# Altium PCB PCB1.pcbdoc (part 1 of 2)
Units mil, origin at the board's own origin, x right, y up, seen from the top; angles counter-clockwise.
Board outline 2441 x 2440.7 mil, 2 copper layers (Top Layer, Bottom Layer), stack 62.2 mil thick; 65 components, 50 nets, 327 pads, 148 vias.
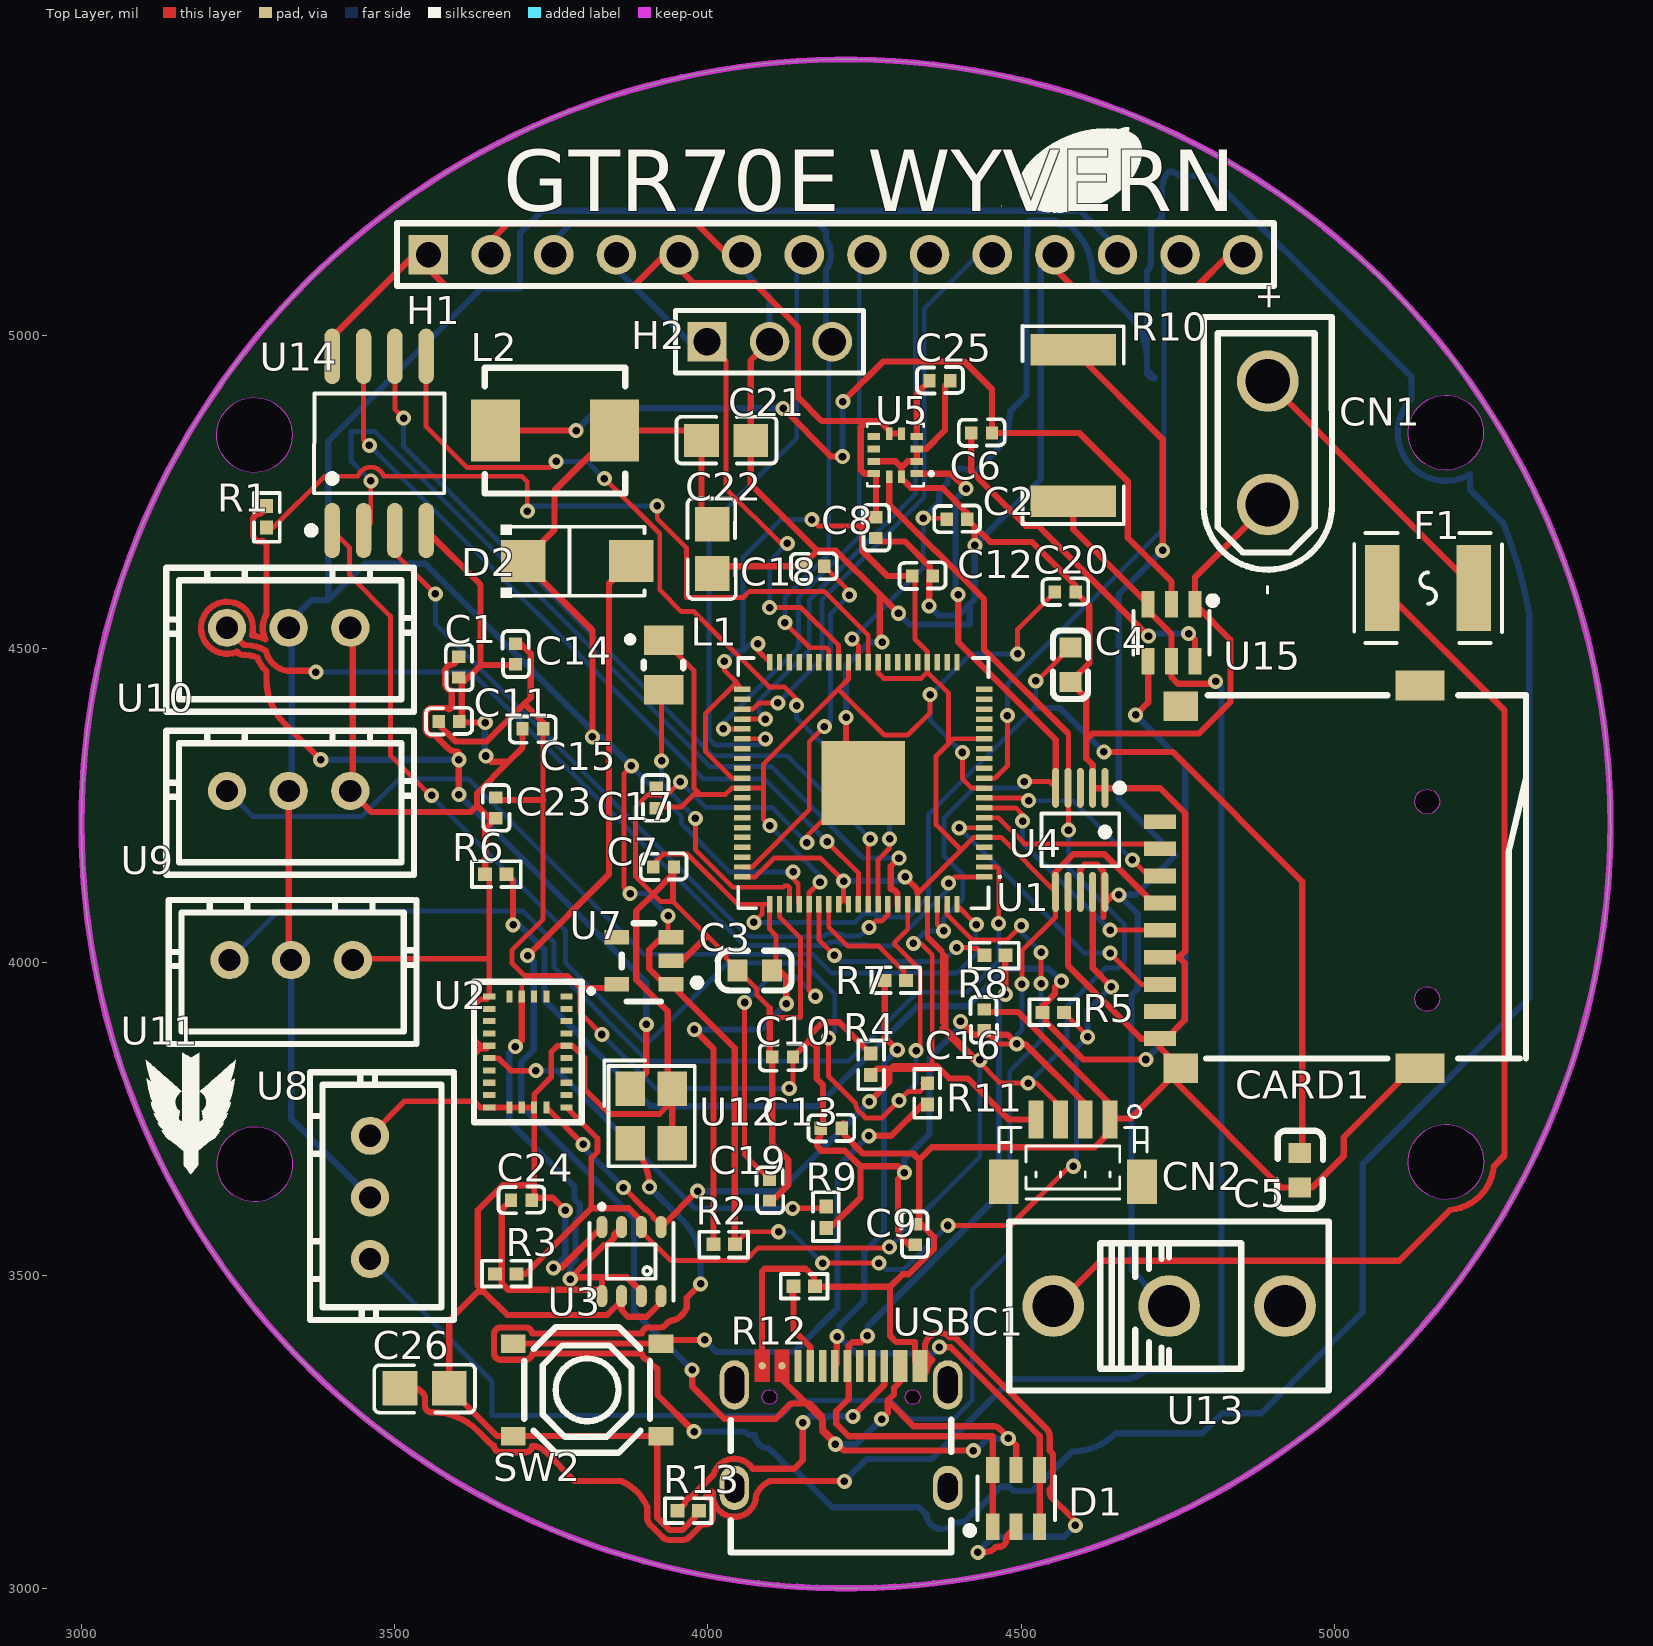
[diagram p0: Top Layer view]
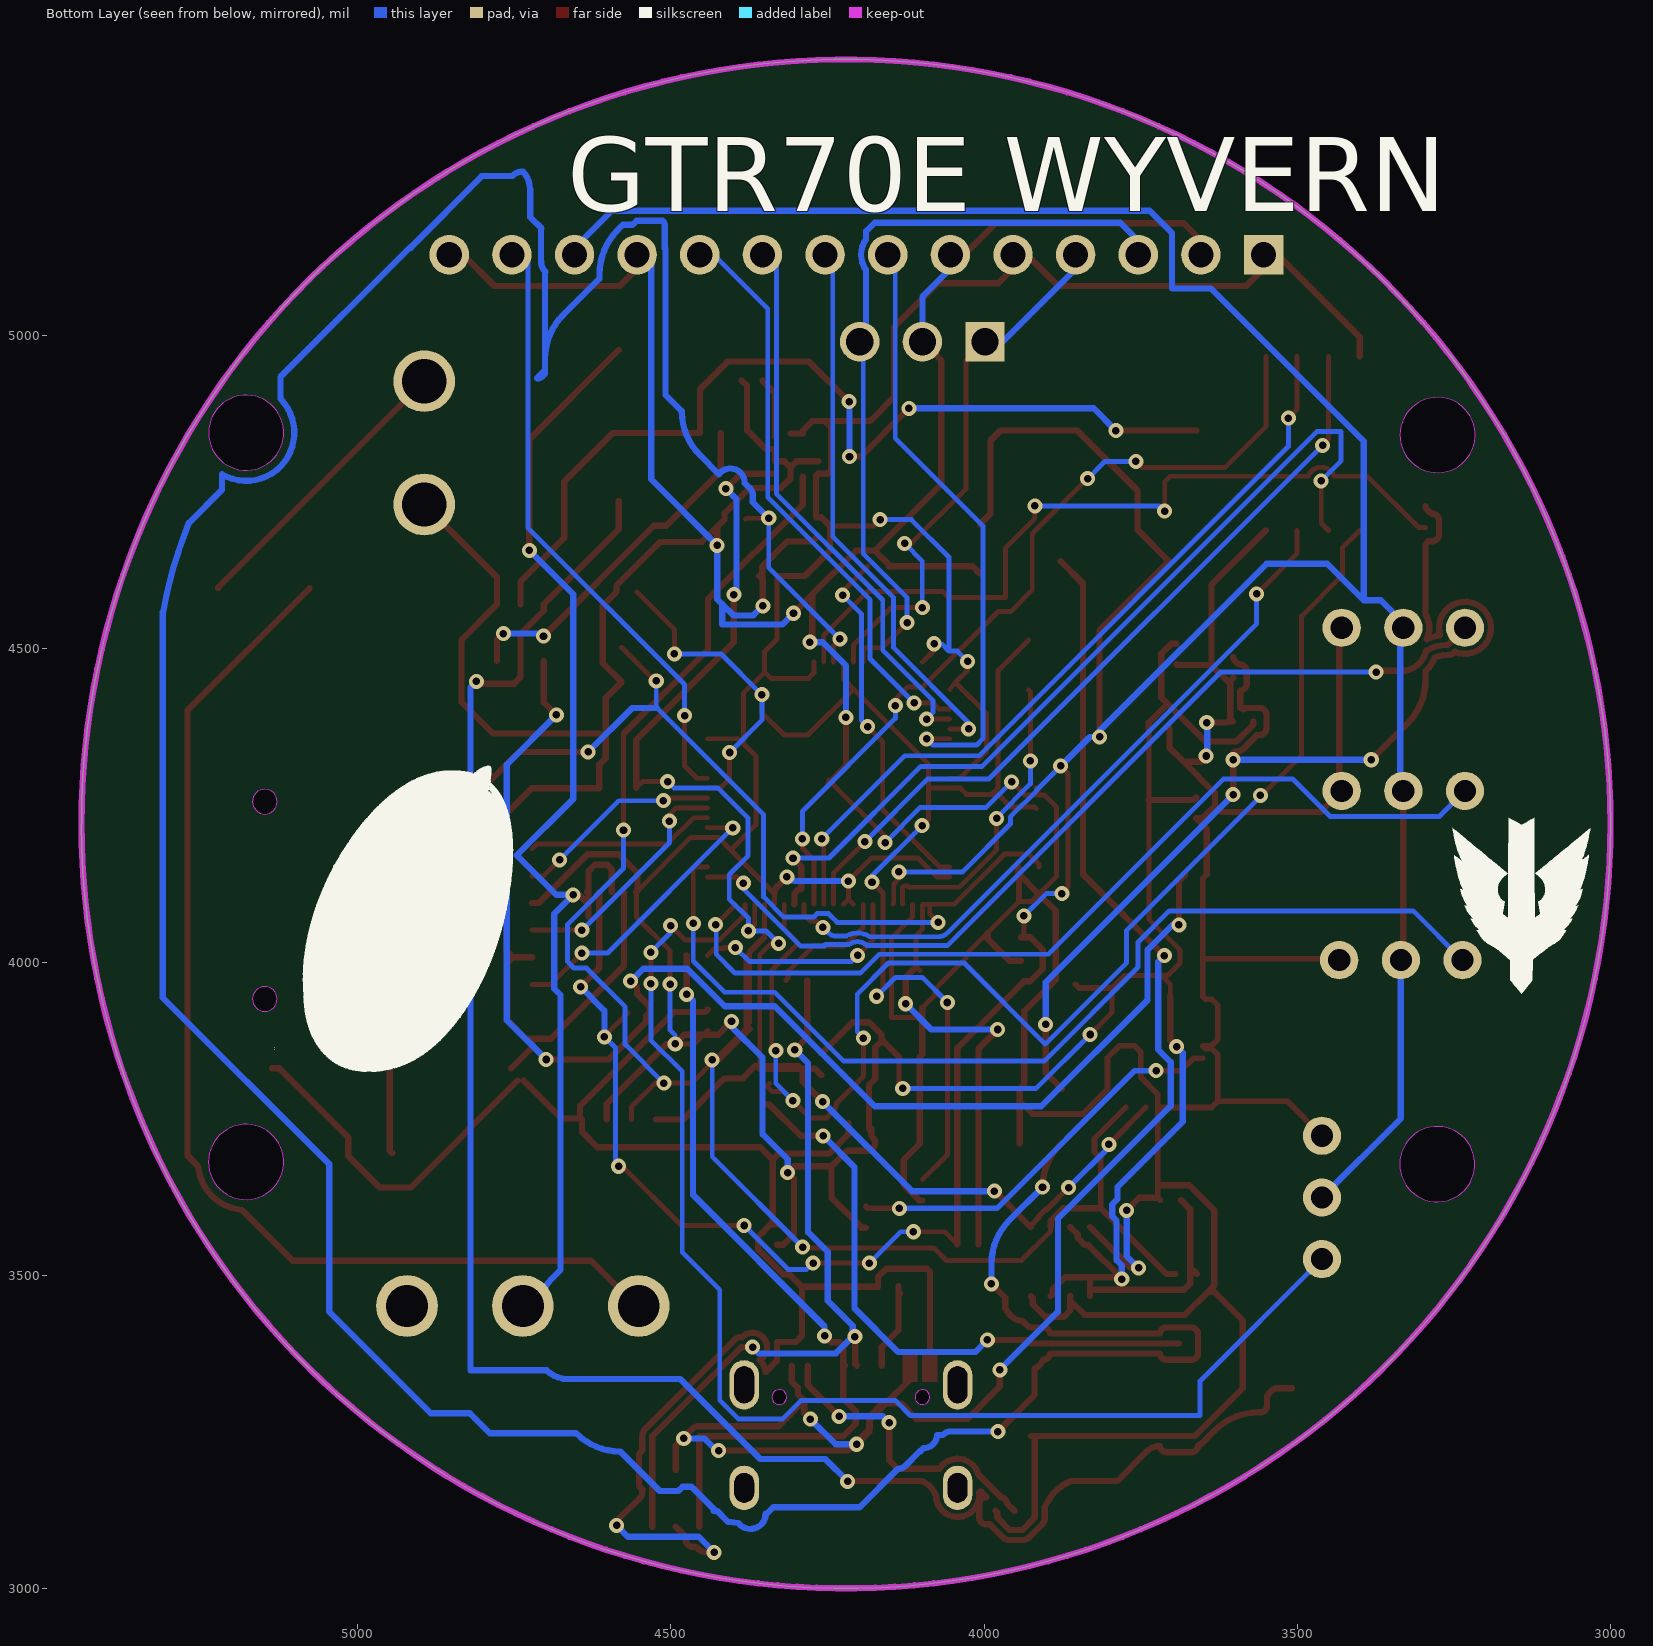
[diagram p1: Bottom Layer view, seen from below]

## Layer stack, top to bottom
Top Solder Mask Layer: solder mask 0.4, Dk 3.3
Top Layer: signal copper 1.4
Dielectric1: surface 59.4, FR4, Dk 4.5
Bottom Layer: signal copper 1.4
Bottom Solder Mask Layer: solder mask 0.4, Dk 3.3

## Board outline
5440.9,4220.5 ccw(c4220.5,4220.5) 3000,4220.5 ccw(c4220.5,4220.5)
cut-out: 3336.2,4841.4 3335.8,4834.5 3334.7,4827.8 3332.7,4821.2 3330.1,4814.9 3326.7,4808.9 3322.7,4803.4 3318,4798.3 3312.8,4793.8 3307.2,4789.9 3301.1,4786.7 3294.7,4784.3 3288.1,4782.5 3281.3,4781.5 3274.5,4781.3 3267.6,4781.9 3260.9,4783.3 3254.4,4785.4 3248.2,4788.3 3242.3,4791.8 3236.9,4796 3231.9,4800.8 3227.6,4806.1 3223.9,4811.8 3220.9,4818 3218.6,4824.4 3217,4831.1 3216.2,4837.9 3216.2,4844.8 3217,4851.6 3218.6,4858.3 3220.9,4864.7 3223.9,4870.9 3227.6,4876.7 3231.9,4882 3236.9,4886.7 3242.3,4890.9 3248.2,4894.5 3254.4,4897.3 3260.9,4899.4 3267.6,4900.8 3274.5,4901.4 3281.3,4901.2 3288.1,4900.2 3294.7,4898.5 3301.1,4896 3307.2,4892.8 3312.8,4888.9 3318,4884.4 3322.7,4879.4 3326.7,4873.8 3330.1,4867.9 3332.7,4861.5 3334.7,4855 3335.8,4848.2
cut-out: 5238,4845 5237.6,4838.1 5236.5,4831.4 5234.5,4824.8 5231.9,4818.5 5228.5,4812.5 5224.5,4807 5219.8,4801.9 5214.7,4797.4 5209,4793.5 5202.9,4790.3 5196.5,4787.9 5189.9,4786.1 5183.1,4785.1 5176.3,4784.9 5169.4,4785.5 5162.7,4786.9 5156.2,4789 5150,4791.9 5144.1,4795.4 5138.7,4799.6 5133.8,4804.4 5129.4,4809.7 5125.7,4815.4 5122.7,4821.6 5120.4,4828.1 5118.8,4834.7 5118,4841.5 5118,4848.4 5118.8,4855.2 5120.4,4861.9 5122.7,4868.3 5125.7,4874.5 5129.4,4880.3 5133.8,4885.6 5138.7,4890.3 5144.1,4894.5 5150,4898.1 5156.2,4900.9 5162.7,4903 5169.4,4904.4 5176.3,4905 5183.1,4904.8 5189.9,4903.8 5196.5,4902.1 5202.9,4899.6 5209,4896.4 5214.7,4892.5 5219.8,4888 5224.5,4883 5228.5,4877.4 5231.9,4871.5 5234.5,4865.1 5236.5,4858.6 5237.6,4851.8
cut-out: 3336.6,3677.2 3336.2,3670.4 3335,3663.6 3333.1,3657.1 3330.4,3650.7 3327,3644.8 3323,3639.2 3318.4,3634.2 3313.2,3629.7 3307.5,3625.8 3301.5,3622.6 3295.1,3620.1 3288.5,3618.4 3281.7,3617.4 3274.8,3617.2 3268,3617.8 3261.3,3619.2 3254.8,3621.3 3248.5,3624.1 3242.6,3627.7 3237.2,3631.9 3232.3,3636.6 3228,3641.9 3224.3,3647.7 3221.2,3653.9 3218.9,3660.3 3217.4,3667 3216.6,3673.8 3216.6,3680.7 3217.4,3687.5 3218.9,3694.2 3221.2,3700.6 3224.3,3706.8 3228,3712.5 3232.3,3717.8 3237.2,3722.6 3242.6,3726.8 3248.5,3730.3 3254.8,3733.2 3261.3,3735.3 3268,3736.7 3274.8,3737.3 3281.7,3737.1 3288.5,3736.1 3295.1,3734.3 3301.5,3731.9 3307.5,3728.7 3313.2,3724.8 3318.4,3720.3 3323,3715.2 3327,3709.7 3330.4,3703.7 3333.1,3697.4 3335,3690.8 3336.2,3684.1
cut-out: 5238.4,3680.8 5238,3674 5236.8,3667.2 5234.9,3660.7 5232.2,3654.3 5228.9,3648.4 5224.8,3642.8 5220.2,3637.8 5215,3633.3 5209.4,3629.4 5203.3,3626.2 5196.9,3623.7 5190.3,3622 5183.5,3621 5176.6,3620.8 5169.8,3621.4 5163.1,3622.8 5156.6,3624.9 5150.3,3627.7 5144.5,3631.3 5139,3635.5 5134.1,3640.2 5129.8,3645.5 5126.1,3651.3 5123,3657.5 5120.7,3663.9 5119.2,3670.6 5118.4,3677.4 5118.4,3684.3 5119.2,3691.1 5120.7,3697.8 5123,3704.2 5126.1,3710.4 5129.8,3716.1 5134.1,3721.4 5139,3726.2 5144.5,3730.4 5150.3,3733.9 5156.6,3736.8 5163.1,3738.9 5169.8,3740.3 5176.6,3740.9 5183.5,3740.7 5190.3,3739.7 5196.9,3737.9 5203.3,3735.5 5209.4,3732.3 5215,3728.4 5220.2,3723.9 5224.8,3718.8 5228.9,3713.3 5232.2,3707.3 5234.9,3701 5236.8,3694.4 5238,3687.7

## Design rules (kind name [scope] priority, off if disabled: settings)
BoardOutlineClearance safeClearance [All] p0: genericclearance=10 ignorepadtopadclearanceinfootprint=FALSE except(0: Arc-SplitContinuation Track-SplitContinuation SMDPad-SplitContinuation THPad-SplitContinuation Via-SplitContinuation Fill-SplitContinuation Poly-SplitContinuation Region-SplitContinuation Text-SplitContinuation)
BoardOutlineClearance otherClearance [All] p0: genericclearance=10 ignorepadtopadclearanceinfootprint=FALSE except(0: Arc-SplitContinuation Track-SplitContinuation SMDPad-SplitContinuation THPad-SplitContinuation Via-SplitContinuation Fill-SplitContinuation Poly-SplitContinuation Region-SplitContinuation Text-SplitContinuation)
Clearance safeClearance [All] p1: gap=7 ignorepadtopadclearanceinfootprint=FALSE
Clearance otherClearance [All] p1: gap=7 ignorepadtopadclearanceinfootprint=FALSE
DiffPairsRouting differentialPair [All] p1: maxuncoupledlength=10 minlimit=6 maxlimit=Infinity mostfreqgap=6 toplayer_minwidth=5 toplayer_prefwidth=10 toplayer_maxwidth=100 bottomlayer_minwidth=5 bottomlayer_prefwidth=10 bottomlayer_maxwidth=100
PasteMaskExpansion pasteMaskExpansion [All] p1: expansion=0
PlaneConnect innerPlane [All] p1: planeconnectstyle=Relief reliefexpansion=20 reliefentries=4 reliefconductorwidth=10 reliefairgap=10
PolygonConnect copperRegion [All] p1: connectstyle=Relief reliefentries=4 reliefconductorwidth=10 polygonreliefangle="90 Angle" airgapwidth=10
RoutingVias viaSize [All] p1: viastyle="Through Hole" holewidth=12.0078 minholewidth=11.811 maxholewidth=236.2204 width=12.0078 minwidth=11.811 maxwidth=236.2204
SolderMaskExpansion solderMaskExpansion [IsVia] p1: useseparateexpansions=TRUE expansion=-1000 expansionbottom=-1000
SolderMaskExpansion solderMaskExpansion [All] p2: useseparateexpansions=TRUE expansion=0.9843 expansionbottom=2.0079
Width trackWidth [All] p1: maxlimit=100 minlimit=5 preferedwidth=10

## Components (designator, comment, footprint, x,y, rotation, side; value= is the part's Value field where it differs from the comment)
C1 "15pF" C0402#1 3602.4,4470.6 r270 top
C2 "15pF" C0402#2 4397.7,4706.8 r0 top
C3 "4.7uF" C0603#1 4074.9,3986.3 r180 top
C4 "4.7uF" C0603#2 4578.8,4474.5 r270 top
C5 "4.7uF" C0603#2 4945,3667.4 r270 top
C6 "100nF" C0402#3 4437.1,4844.6 r0 top
C7 "100nF" C0402#2 3929.2,4151.7 r0 top
C8 "100nF" C0402#3 4268.2,4693.5 r270 top
C9 "100nF" C0402#3 4330.8,3565.1 r90 top
C10 "100nF" C0402#2 4119.5,3848.5 r180 top
C11 "100nF" C0402#1 3586.7,4384 r0 top
C12 "100nF" C0402#1 4342.6,4616.3 r0 top
C13 "100nF" C0402#2 4196.9,3734.4 r0 top
C14 "100nF" C0402#1 3692.8,4491.8 r270 top
C15 "100nF" C0402#2 3720.6,4372.2 r180 top
C16 "100nF" C0402#1 4441,3907.6 r90 top
C17 "100nF" C0402#2 3917.4,4261.9 r90 top
C18 "100nF" C0402#2 4169.4,4632 r180 top
C19 "100nF" C0402#3 4098.5,3635.9 r270 top
C20 "100nF" C0402#3 4570.5,4590.6 r0 top
C21 "22uF" C0805#1 4029.2,4832.6 r0 top
C22 "22uF" C0805#2 4006.6,4659.6 r270 top
C23 "100nF" C0402#2 3661.5,4246.2 r270 top
C24 "100nF" C0402#3 3702.2,3619.7 r0 top
C25 "100nF" C0402#2 4370.4,4928.2 r0 top
C26 "10uF" C0805#3 3547.7,3319.7 r0 top
CARD1 "TF-01A" TF-SMD_TF-01A 4929.2,4135.9 r90 top
CN1 "XT30UPB-M" CONN-TH_XT30UPB-M 4893.8,4828.9 r90 top
CN2 "BM04B-SRSS-TB(LF)(SN)" CONN-SMD_BM04B-SRSS-TB 4582.8,3698.9 r180 top
D1 "USBLC6-2SC6" SOT-23-6_L2.9-W1.6-P0.95-LS2.8-BL#1 4492.2,3143.8 r0 top
D2 "SS14" SMA_L4.4-W2.6-LS5.0-RD 3791.4,4639.9 r0 top
F1 "SMD1812P260TF/16" F1812 5149.7,4597 r0 top
H1 "2011-1X14G00SB" HDR-TH_14P-P2.54-V-M_4 4203.9,5129.2 r0 top
H2 "2.54-1*3P针" HDR-TH_3P-P2.54-V-M-1 4098.5,4990.3 r0 top
L1 "3.3uH" IND-SMD_L2.0-W1.6_AOTA-B201610S3R3-101-T 3929.2,4474.5 r90 top
L2 "2.2uH" IND-SMD_L5.7-W5.1 3756,4848.5 r0 top
R1 "1kΩ" R0402#1 3295.4,4710.7 r90 top
R2 "33Ω" R0402#2 4026.1,3549.4 r0 top
R3 "10kΩ" R0402#2 3677.2,3502.1 r180 top
R4 "10kΩ" R0402#1 4259.9,3836.7 r90 top
R5 "56kΩ" R0402#1 4551.3,3919.4 r180 top
R6 "10.2kΩ" R0402#3 3661.5,4139.9 r180 top
R7 "27Ω" R0402#3 4299.3,3970.6 r180 top
R8 "27Ω" R0402#1 4458.3,4010.6 r0 top
R9 "10kΩ" R0402#2 4189.1,3592.6 r270 top
R10 "10mΩ" R2512 4583.1,4856.5 r270 top
R11 "1kΩ" R0402#1 4350.5,3789.5 r270 top
R12 "5.1kΩ" R0402#1 4153.6,3482.4 r0 top
R13 "5.1kΩ" R0402#2 3968.6,3124.1 r0 top
SW2 "TS-1187A-B-A-B" SW-SMD_4P-L5.1-W5.1-P3.70-LS6.5-TL_H1.5 3807.2,3317 r0 top
U1 "RP2350B" QFN-80_L10.0-W10.0-P0.40-TL-EP3.4 4248.1,4285.6 r180 top
U2 "BNO055" LGA-28_L5.2-W3.8-P0.50-BL 3712.7,3856.4 r180 top
U3 "BME680" LGA-8_L3.0-W3.0-P0.80-TR 3878,3521.8 r90 top
U4 "INA226AIDGSR" MSOP-10_L3.0-W3.0-P0.50-LS5.0-BL 4594.6,4195 r180 top
U5 "LIS3MDLTR" LGA-12_L2.0-W2.0-P0.50-BL 4299.3,4809.2 r90 top
U7 "AP2112K-3.3TRG1" SOT-23-5_L2.9-W1.6-P0.95-LS2.8-BR 3897.7,4002.1 r0 top
U8 "B3B-XH-A(LF)(SN)" CONN-TH_3P-P2.50_A2501WV2-3P#1 3460.7,3624.1 r90 top
U9 "B3B-XH-A(LF)(SN)" CONN-TH_3P-P2.50_A2501WV2-3P#2 3330.8,4273.2 r0 top
U10 "B3B-XH-A(LF)(SN)" CONN-TH_3P-P2.50_A2501WV2-3P#2 3330.8,4533.6 r0 top
U11 "B3B-XH-A(LF)(SN)" CONN-TH_3P-P2.50_A2501WV2-3P#1 3334.7,4003 r0 top
U12 "12MHz" CRYSTAL-SMD_4P-L3.2-W2.5-BL 3909.5,3754.1 r270 top
U13 "SS-12D10G5" SW-TH_SS-12D10L9 4736.3,3450.9 r0 top
U14 "W25Q32JVSSIQ" SOIC-8_L5.3-W5.3-P1.27-LS8.0-BL 3475.3,4827.9 r0 top
U15 "TPS564201DDCR" SOT-23-6_L2.9-W1.6-P0.95-LS2.8-BL#2 4740.2,4525.7 r180 top
USBC1 "TYPE-C-31-M-12" USB-C_SMD-TYPE-C-31-M-12_1 4212.7,3258 r0 top

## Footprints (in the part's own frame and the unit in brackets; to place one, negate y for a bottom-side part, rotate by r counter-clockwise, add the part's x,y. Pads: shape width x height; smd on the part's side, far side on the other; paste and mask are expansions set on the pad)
C0402#1 [mil]
  rect 19.7x21.3 smd paste+0 mask+0: 1(-16.5,0) 2(16.5,0)
  silkscreen extent -36,-21 37,22
C0402#2 [mil]
  rect 19.7x21.3 smd paste+0 mask+0: 1(-16.5,0) 2(16.6,0)
  silkscreen extent -36,-21 37,22
C0402#3 [mil]
  rect 19.7x21.3 smd paste+0 mask+0: 1(-16.6,0) 2(16.5,0)
  silkscreen extent -36,-21 37,22
C0603#1 [mil]
  rect 31.5x35.4 smd: 1(-27.5,0) 2(27.6,0)
  silkscreen extent -59,-32 59,32
C0603#2 [mil]
  rect 31.5x35.4 smd paste+0 mask+0: 1(-27.6,0) 2(27.5,0)
  silkscreen extent -55,-28 55,28
C0805#1 [mil]
  rect 55.5x53.1 smd paste+0 mask+0: 1(-39.4,0) 2(39.4,0)
  silkscreen extent -79,-37 80,38
C0805#2 [mil]
  rect 55.5x55.1 smd paste-3937 mask+0: 1(-39.4,0) 2(39.4,0)
  silkscreen extent -80,-39 80,38
C0805#3 [mil]
  rect 55.5x55.1 smd paste-3937 mask+0: 1(-39.3,0) 2(39.4,0)
  silkscreen extent -80,-39 80,38
CONN-SMD_BM04B-SRSS-TB [mil]
  rect 47.2x70.9 smd: 0(-110.2,49.7) 0(110.3,49.7)
  rect 23.6x61 smd: 1(-59,-49.7) 2(-19.6,-49.7) 3(19.7,-49.7) 4(59.1,-49.7)
  silkscreen extent -118,-72 118,77
CONN-TH_3P-P2.50_A2501WV2-3P#1 [mil]
  round 61 hole 35.4: 1(-98.4,0) 2(0,0) 3(98.5,0)
  silkscreen extent -196,-134 200,96
CONN-TH_3P-P2.50_A2501WV2-3P#2 [mil]
  round 61 hole 35.4: 1(-98.4,0) 2(0,0) 3(98.4,0)
  silkscreen extent -196,-134 200,96
CONN-TH_XT30UPB-M [mil]
  round 98.4 hole 70.9: 1(-98.5,0) 2(98.4,0)
  silkscreen extent -203,-102 201,102
CRYSTAL-SMD_4P-L3.2-W2.5-BL [mil]
  rect 55.1x47.2 smd paste+0 mask+0: 1(-43.3,-33.4) 2(43.4,-33.4) 3(43.4,33.5) 4(-43.3,33.5)
  silkscreen extent -89,-75 80,70
F1812 [mil]
  rect 55.4x137.8 smd paste-3937 mask+2: 1(-72.9,0) 2(73,0)
  silkscreen extent -118,-88 118,88
HDR-TH_3P-P2.54-V-M-1 [mil]
  rect 62x63 hole 43.3: 1(-100,0)
  round 63 hole 43.3: 2(0,0) 3(100,0)
  silkscreen extent -150,-50 150,50
HDR-TH_14P-P2.54-V-M_4 [mil]
  rect 63x63 hole 40.2: 1(-650,0)
  round 63 hole 40.2: 2(-550,0) 3(-450,0) 4(-350,0) 5(-250,0) 6(-150,0) 7(-50,0) 8(50,0) 9(150,0) 10(250,0) 11(350,0) 12(450,0) 13(550,0) 14(650,0)
  silkscreen extent -700,-50 700,50
IND-SMD_L2.0-W1.6_AOTA-B201610S3R3-101-T [mil]
  rect 47.2x63 smd paste+0 mask+0: 1(-40,0) 2(39.4,0)
  silkscreen extent -6,-32 46,58
IND-SMD_L5.7-W5.1 [mil]
  rect 78.7x98.4 smd paste+0 mask+2: 1(-95,0) 2(95,0)
  silkscreen extent -112,-100 112,100
LGA-8_L3.0-W3.0-P0.80-TR [mil]
  oval 35.4x17.6 smd paste+0 mask+0: 1(55.1,47.2) 2(55.1,15.7) 3(55.1,-15.8) 4(55.1,-47.3) 5(-55.1,-47.3) 6(-55.1,-15.8) 7(-55.1,15.7) 8(-55.1,47.2)
  silkscreen extent -62,-67 92,67
LGA-12_L2.0-W2.0-P0.50-BL [mil]
  rect 11x19.7 smd: 1(-29.6,-34.4) 2(-9.9,-34.4) 3(9.8,-34.4) 4(29.5,-34.4) 7(29.5,34.5) 8(9.8,34.5) 9(-9.9,34.5) 10(-29.6,34.5)
  rect 19.7x11 smd: 5(34.4,-9.8) 6(34.4,9.8) 11(-34.5,9.8) 12(-34.5,-9.8)
  silkscreen extent -50,-60 50,45
LGA-28_L5.2-W3.8-P0.50-BL [mil]
  rect 19.7x9.8 smd: 1(-61.5,-88.6) 6(61.6,-88.6) 7(61.6,-68.9) 8(61.6,-49.2) 9(61.6,-29.5) 10(61.6,-9.9) 11(61.6,9.8) 12(61.6,29.5) 13(61.6,49.2) 14(61.6,68.9) 15(61.6,88.6) 20(-61.5,88.6) 21(-61.5,68.9) 22(-61.5,49.2) 23(-61.5,29.5) 24(-61.5,9.8) 25(-61.5,-9.9) 26(-61.5,-29.5) 27(-61.5,-49.2) 28(-61.5,-68.9)
  rect 9.8x19.7 smd: 2(-29.5,-88.6) 3(-9.8,-88.6) 4(9.9,-88.6) 5(29.5,-88.6) 16(29.5,88.6) 17(9.9,88.6) 18(-9.8,88.6) 19(-29.5,88.6)
  silkscreen extent -105,-112 86,112
MSOP-10_L3.0-W3.0-P0.50-LS5.0-BL [mil]
  oval 11x63.8 smd paste+0 mask+0: 1(-39.3,-83.1) 2(-19.6,-83.1) 3(0,-83.1) 4(19.7,-83.1) 5(39.4,-83.1) 6(39.4,83.1) 7(19.7,83.1) 8(0,83.1) 9(-19.6,83.1) 10(-39.3,83.1)
  silkscreen extent -69,-89 62,42
QFN-80_L10.0-W10.0-P0.40-TL-EP3.4 [mil]
  rect 26.2x8.7 smd: 1(-193.2,149.7) 2(-193.2,133.9) 3(-193.2,118.2) 4(-193.2,102.4) 5(-193.2,86.7) 6(-193.2,70.9) 7(-193.2,55.2) 8(-193.2,39.4) 9(-193.2,23.7) 10(-193.2,7.9) 11(-193.2,-7.8) 12(-193.2,-23.6) 13(-193.2,-39.3) 14(-193.2,-55.1) 15(-193.2,-70.8) 16(-193.2,-86.6) 17(-193.2,-102.3) 18(-193.2,-118.1) 19(-193.2,-133.8) 20(-193.2,-149.6) 41(193.2,-149.6) 42(193.2,-133.8) 43(193.2,-118.1) 44(193.2,-102.3) 45(193.2,-86.6) 46(193.2,-70.8) 47(193.2,-55.1) 48(193.2,-39.3) 49(193.2,-23.6) 50(193.2,-7.8) 51(193.2,7.9) 52(193.2,23.7) 53(193.2,39.4) 54(193.2,55.2) 55(193.2,70.9) 56(193.2,86.7) 57(193.2,102.4) 58(193.2,118.2) 59(193.2,133.9) 60(193.2,149.7)
  rect 8.7x26.2 smd: 21(-149.6,-193.2) 22(-133.9,-193.2) 23(-118.1,-193.2) 24(-102.4,-193.2) 25(-86.6,-193.2) 26(-70.9,-193.2) 27(-55.1,-193.2) 28(-39.4,-193.2) 29(-23.6,-193.2) 30(-7.9,-193.2) 31(7.9,-193.2) 32(23.6,-193.2) 33(39.4,-193.2) 34(55.1,-193.2) 35(70.9,-193.2) 36(86.6,-193.2) 37(102.3,-193.2) 38(118.1,-193.2) 39(133.8,-193.2) 40(149.6,-193.2) 61(149.6,193.3) 62(133.8,193.3) 63(118.1,193.3) 64(102.3,193.3) 65(86.6,193.3) 66(70.9,193.3) 67(55.1,193.3) 68(39.4,193.3) 69(23.6,193.3) 70(7.9,193.3) 71(-7.9,193.3) 72(-23.6,193.3) 73(-39.4,193.3) 74(-55.1,193.3) 75(-70.9,193.3) 76(-86.6,193.3) 77(-102.4,193.3) 78(-118.1,193.3) 79(-133.9,193.3) 80(-149.6,193.3)
  rect 133.9x133.9 smd: 81(0,0)
  silkscreen extent -220,-200 200,200
R0402#1 [mil]
  rect 22.3x21.3 smd paste-3937 mask+0: 1(-17,0) 2(17.1,0)
  silkscreen extent -40,-21 38,20
R0402#2 [mil]
  rect 22.3x21.3 smd paste-3937 mask+0: 1(-17.1,0) 2(17,0)
  silkscreen extent -40,-21 38,20
R0402#3 [mil]
  rect 22.3x21.3 smd paste-3937 mask+0: 1(-17,0) 2(17,0)
  silkscreen extent -40,-21 38,20
R2512 [mil]
  rect 50.5x136.1 smd paste-3937 mask+2: 1(-120.7,0) 2(120.7,0)
  silkscreen extent -159,-81 157,81
SMA_L4.4-W2.6-LS5.0-RD [mil]
  rect 70.9x66.9 smd: 1(-86.3,0) 2(86.3,0)
  silkscreen extent -122,-58 107,58
SOIC-8_L5.3-W5.3-P1.27-LS8.0-BL [mil]
  oval 24.8x88.6 smd: 1(-75,-139) 2(-25,-139) 3(25,-139) 4(75,-139) 5(75,139) 6(25,139) 7(-25,139) 8(-75,139)
  silkscreen extent -114,-145 104,80
SOT-23-5_L2.9-W1.6-P0.95-LS2.8-BR [mil]
  rect 39.4x23.6 smd paste+0 mask+2: 1(43.3,-37.4) 2(43.3,0) 3(43.3,37.4) 4(-43.3,37.4) 5(-43.3,-37.4)
  silkscreen extent -35,-65 91,60
SOT-23-6_L2.9-W1.6-P0.95-LS2.8-BL#1 [mil]
  rect 20.9x42.2 smd: 1(-37.4,-45.2) 2(0,-45.2) 3(37.4,-45.2) 4(37.4,45.3) 5(0,45.3) 6(-37.4,45.3)
  silkscreen extent -80,-57 62,35
SOT-23-6_L2.9-W1.6-P0.95-LS2.8-BL#2 [mil]
  rect 20.9x42.2 smd: 1(-37.4,-45.2) 2(0,-45.2) 3(37.4,-45.2) 4(37.4,45.2) 5(0,45.2) 6(-37.4,45.2)
  silkscreen extent -72,-57 61,35
SW-SMD_4P-L5.1-W5.1-P3.70-LS6.5-TL_H1.5 [mil]
  rect 39.4x29.5 smd: 1(-118.1,73.9) 2(118.1,73.9) 3(-118.1,-73.8) 4(118.1,-73.8)
  silkscreen extent -100,-100 100,100
SW-TH_SS-12D10L9 [mil]
  round 98.4 hole 66.9: 1(-185,0) 2(0,0) 3(185,0)
  silkscreen extent -255,-135 255,135
TF-SMD_TF-01A [mil]
  rect 23.6x51.2 smd: 1(88.2,207.7) 2(44.9,207.7) 3(1.6,207.7) 4(-41.7,207.7) 5(-85,207.7) 6(-128.3,207.7) 7(-171.6,207.7) 8(-214.9,207.7) 9(-258.2,207.7)
  rect 47.2x55.1 smd: 10(-305.5,174.2) 13(272.5,174.2)
  rect 47.2x78.7 smd paste+0 mask+0: 11(-305.5,-207.7) 12(305.6,-207.7)
  Board Outline Layer lines w0.1: -194.8,-199.5 -198.7,-199.8 -202.4,-201 -205.8,-202.8 -208.8,-205.2 -211.2,-208.2 -213,-211.6 -214.1,-215.3 -214.5,-219.1 -214.1,-223 -213,-226.7 -211.2,-230.1 -208.8,-233.1 -205.8,-235.5 -202.4,-237.3 -198.7,-238.5 -194.8,-238.8 -191,-238.5 -187.3,-237.3 -183.9,-235.5 -180.9,-233.1 -178.5,-230.1 -176.6,-226.7 -175.5,-223 -175.2,-219.1 -175.5,-215.3 -176.6,-211.6 -178.5,-208.2 -180.9,-205.2 -183.9,-202.8 -187.3,-201 -191,-199.8 -194.8,-199.5 ; 120.1,-199.5 116.3,-199.8 112.6,-201 109.2,-202.8 106.2,-205.2 103.8,-208.2 101.9,-211.6 100.8,-215.3 100.4,-219.1 100.8,-223 101.9,-226.7 103.8,-230.1 106.2,-233.1 109.2,-235.5 112.6,-237.3 116.3,-238.5 120.1,-238.8 124,-238.5 127.7,-237.3 131.1,-235.5 134,-233.1 136.5,-230.1 138.3,-226.7 139.4,-223 139.8,-219.1 139.4,-215.3 138.3,-211.6 136.5,-208.2 134,-205.2 131.1,-202.8 127.7,-201 124,-199.8 120.1,-199.5
  Board Outline Layer region: -175.2,-219.1 -175.5,-223 -176.6,-226.7 -178.5,-230.1 -180.9,-233.1 -183.9,-235.5 -187.3,-237.3 -191,-238.5 -194.8,-238.8 -198.7,-238.5 -202.4,-237.3 -205.8,-235.5 -208.8,-233.1 -211.2,-230.1 -213,-226.7 -214.1,-223 -214.5,-219.1 -214.1,-215.3 -213,-211.6 -211.2,-208.2 -208.8,-205.2 -205.8,-202.8 -202.4,-201 -198.7,-199.8 -194.8,-199.5 -191,-199.8 -187.3,-201 -183.9,-202.8 -180.9,-205.2 -178.5,-208.2 -176.6,-211.6 -175.5,-215.3
  Board Outline Layer region: -175.2,-219.1 -175.5,-223 -176.6,-226.7 -178.5,-230.1 -180.9,-233.1 -183.9,-235.5 -187.3,-237.3 -191,-238.5 -194.8,-238.8 -198.7,-238.5 -202.4,-237.3 -205.8,-235.5 -208.8,-233.1 -211.2,-230.1 -213,-226.7 -214.1,-223 -214.5,-219.1 -214.1,-215.3 -213,-211.6 -211.2,-208.2 -208.8,-205.2 -205.8,-202.8 -202.4,-201 -198.7,-199.8 -194.8,-199.5 -191,-199.8 -187.3,-201 -183.9,-202.8 -180.9,-205.2 -178.5,-208.2 -176.6,-211.6 -175.5,-215.3
  Board Outline Layer region: 139.8,-219.1 139.4,-223 138.3,-226.7 136.5,-230.1 134,-233.1 131.1,-235.5 127.7,-237.3 124,-238.5 120.1,-238.8 116.3,-238.5 112.6,-237.3 109.2,-235.5 106.2,-233.1 103.8,-230.1 101.9,-226.7 100.8,-223 100.4,-219.1 100.8,-215.3 101.9,-211.6 103.8,-208.2 106.2,-205.2 109.2,-202.8 112.6,-201 116.3,-199.8 120.1,-199.5 124,-199.8 127.7,-201 131.1,-202.8 134,-205.2 136.5,-208.2 138.3,-211.6 139.4,-215.3
  Board Outline Layer region: 139.8,-219.1 139.4,-223 138.3,-226.7 136.5,-230.1 134,-233.1 131.1,-235.5 127.7,-237.3 124,-238.5 120.1,-238.8 116.3,-238.5 112.6,-237.3 109.2,-235.5 106.2,-233.1 103.8,-230.1 101.9,-226.7 100.8,-223 100.4,-219.1 100.8,-215.3 101.9,-211.6 103.8,-208.2 106.2,-205.2 109.2,-202.8 112.6,-201 116.3,-199.8 120.1,-199.5 124,-199.8 127.7,-201 131.1,-202.8 134,-205.2 136.5,-208.2 138.3,-211.6 139.4,-215.3
  Multi-Layer board cut-out: -175.2,-219.1 -175.5,-223 -176.6,-226.7 -178.5,-230.1 -180.9,-233.1 -183.9,-235.5 -187.3,-237.3 -191,-238.5 -194.8,-238.8 -198.7,-238.5 -202.4,-237.3 -205.8,-235.5 -208.8,-233.1 -211.2,-230.1 -213,-226.7 -214.1,-223 -214.5,-219.1 -214.1,-215.3 -213,-211.6 -211.2,-208.2 -208.8,-205.2 -205.8,-202.8 -202.4,-201 -198.7,-199.8 -194.8,-199.5 -191,-199.8 -187.3,-201 -183.9,-202.8 -180.9,-205.2 -178.5,-208.2 -176.6,-211.6 -175.5,-215.3
  Multi-Layer board cut-out: 139.8,-219.1 139.4,-223 138.3,-226.7 136.5,-230.1 134,-233.1 131.1,-235.5 127.7,-237.3 124,-238.5 120.1,-238.8 116.3,-238.5 112.6,-237.3 109.2,-235.5 106.2,-233.1 103.8,-230.1 101.9,-226.7 100.8,-223 100.4,-219.1 100.8,-215.3 101.9,-211.6 103.8,-208.2 106.2,-205.2 109.2,-202.8 112.6,-201 116.3,-199.8 120.1,-199.5 124,-199.8 127.7,-201 131.1,-202.8 134,-205.2 136.5,-208.2 138.3,-211.6 139.4,-215.3
  silkscreen extent -290,-377 290,134
USB-C_SMD-TYPE-C-31-M-12_1 [mil]
  oval 47.2x78.7 hole 31.5 slot 59.1 at 90 deg paste+0 mask+2: 1(170.3,67.1) 4(-170.3,67.1)
  oval 47.2x70.9 hole 31.5 slot 47.2 at 90 deg paste+0 mask+2: 2(170.3,-97.4) 3(-170.3,-97.4)
  round 11.8 smd: A1B12(-126,97.4) A4B9(-94.5,97.4)
  rect 11.8x51.2 smd paste-3937 mask+0: A5(-49.2,97.4) A6(-9.9,97.4) A7(9.8,97.4) A8(49.2,97.4) B5(68.9,97.4) B6(29.5,97.4) B7(-29.6,97.4) B8(-68.9,97.4)
  rect 23.6x51.2 smd paste-3937 mask+0: B1A12(126,97.4) B4A9(94.5,97.4)
  Top Layer region: -114.2,71.8 -126,71.8 -126,71.8 -137.8,71.8 -137.8,123 -126,123 -126,123 -114.2,123
  Top Layer region: -82.7,71.8 -94.5,71.8 -94.5,71.8 -106.3,71.8 -106.3,123 -94.5,123 -94.5,123 -82.7,123
  Board Outline Layer lines w0.1: -125.9,46 -125.2,43.1 -123.7,40.5 -121.7,38.4 -119.2,36.8 -116.4,35.9 -113.5,35.7 -110.5,36.2 -107.9,37.5 -105.6,39.4 -103.8,41.8 -102.8,44.5 -102.4,47.5 -102.8,50.4 -103.8,53.1 -105.6,55.5 -107.9,57.4 -110.5,58.7 -113.5,59.2 -116.4,59.1 -119.2,58.1 -121.7,56.6 -123.7,54.4 -125.2,51.8 -125.9,48.9 -125.9,46 ; 102.4,46 103.2,43.1 104.6,40.5 106.6,38.4 109.1,36.8 111.9,35.9 114.9,35.7 117.8,36.2 120.5,37.5 122.8,39.4 124.5,41.8 125.6,44.5 126,47.5 125.6,50.4 124.5,53.1 122.8,55.5 120.5,57.4 117.8,58.7 114.9,59.2 111.9,59.1 109.1,58.1 106.6,56.6 104.6,54.4 103.2,51.8 102.4,48.9 102.4,46
  Board Outline Layer region: -102.4,47.5 -102.8,44.5 -103.8,41.8 -105.6,39.4 -107.9,37.5 -110.5,36.2 -113.5,35.7 -116.4,35.9 -119.2,36.8 -121.7,38.4 -123.7,40.5 -125.2,43.1 -125.9,46 -125.9,48.9 -125.2,51.8 -123.7,54.4 -121.7,56.6 -119.2,58.1 -116.4,59.1 -113.5,59.2 -110.5,58.7 -107.9,57.4 -105.6,55.5 -103.8,53.1 -102.8,50.4
  Board Outline Layer region: -102.4,47.5 -102.8,44.5 -103.8,41.8 -105.6,39.4 -107.9,37.5 -110.5,36.2 -113.5,35.7 -116.4,35.9 -119.2,36.8 -121.7,38.4 -123.7,40.5 -125.2,43.1 -125.9,46 -125.9,48.9 -125.2,51.8 -123.7,54.4 -121.7,56.6 -119.2,58.1 -116.4,59.1 -113.5,59.2 -110.5,58.7 -107.9,57.4 -105.6,55.5 -103.8,53.1 -102.8,50.4
  Board Outline Layer region: 126,47.5 125.6,44.5 124.5,41.8 122.8,39.4 120.5,37.5 117.8,36.2 114.9,35.7 111.9,35.9 109.1,36.8 106.6,38.4 104.6,40.5 103.2,43.1 102.4,46 102.4,48.9 103.2,51.8 104.6,54.4 106.6,56.6 109.1,58.1 111.9,59.1 114.9,59.2 117.8,58.7 120.5,57.4 122.8,55.5 124.5,53.1 125.6,50.4
  Board Outline Layer region: 126,47.5 125.6,44.5 124.5,41.8 122.8,39.4 120.5,37.5 117.8,36.2 114.9,35.7 111.9,35.9 109.1,36.8 106.6,38.4 104.6,40.5 103.2,43.1 102.4,46 102.4,48.9 103.2,51.8 104.6,54.4 106.6,56.6 109.1,58.1 111.9,59.1 114.9,59.2 117.8,58.7 120.5,57.4 122.8,55.5 124.5,53.1 125.6,50.4
  Multi-Layer board cut-out: -102.4,47.5 -102.8,44.5 -103.8,41.8 -105.6,39.4 -107.9,37.5 -110.5,36.2 -113.5,35.7 -116.4,35.9 -119.2,36.8 -121.7,38.4 -123.7,40.5 -125.2,43.1 -125.9,46 -125.9,48.9 -125.2,51.8 -123.7,54.4 -121.7,56.6 -119.2,58.1 -116.4,59.1 -113.5,59.2 -110.5,58.7 -107.9,57.4 -105.6,55.5 -103.8,53.1 -102.8,50.4
  Multi-Layer board cut-out: 126,47.5 125.6,44.5 124.5,41.8 122.8,39.4 120.5,37.5 117.8,36.2 114.9,35.7 111.9,35.9 109.1,36.8 106.6,38.4 104.6,40.5 103.2,43.1 102.4,46 102.4,48.9 103.2,51.8 104.6,54.4 106.6,56.6 109.1,58.1 111.9,59.1 114.9,59.2 117.8,58.7 120.5,57.4 122.8,55.5 124.5,53.1 125.6,50.4
  silkscreen extent -176,-201 176,11

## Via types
v1: diameter 24, hole 12, Top Layer to Bottom Layer, 148 vias

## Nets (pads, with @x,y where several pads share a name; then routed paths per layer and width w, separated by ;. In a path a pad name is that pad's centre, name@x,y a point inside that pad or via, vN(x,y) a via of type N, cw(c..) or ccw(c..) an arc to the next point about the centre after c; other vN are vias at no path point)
$1N357: CN2.3 R3.1 U1.77 U2.20 U3.3 U4.4 U5.11 | length 3147.5
  Top Layer w7.8: U3.3@3893.8,3576.9 3893.8,3570.3 3940.5,3523.6 4060.5,3523.6 4080.5,3543.6 4288.4,3543.6 v1(4289.9,3545) ; U1.77@4350.5,4092.3 4350.5,4038.6 ; v1(4434.1,3843.9) v1@4429.9,3843.9 ; CN2.3@4563.1,3748.6 4563.1,3768.6 4524.9,3806.8 v1(4511.3,3806.8) 4467,3806.8 v1@4429.9,3843.9 ; 4574.9,4364.9 4575.7,4364.1 v1(4575.7,4210.5) ; 4350.5,4038.6 4353.1,4038.6 4374.1,4017.6 4374.1,4015 ; 4350.5,4038.6 4374.1,4015 ; 4374.1,4015 4380.5,4008.6 4380.5,3901.2 ; 4374.1,4015 4374.1,3903.7 4376.5,3901.2 4380.5,3901.2 ; 4380.5,3901.2 4372.6,3893.4 4422,3843.9 v1@4429.9,3843.9 ; 4380.5,3901.2 4380.5,3893.4 v1@4429.9,3843.9
  Top Layer w8.9: U2.20@3774.2,3767.8 3823.8,3718.3 3823.8,3696.9 3813.8,3686.9 3813.8,3606.9
  Top Layer w9.9: U5.11@4289.5,4774.7 4289.5,4730.3 4441,4578.8 4441,4498.8 4574.9,4364.9
  Top Layer w10: R3.1@3694.3,3502.1 3709,3502.1 3813.8,3606.9 3873.8,3606.9 3893.8,3586.9 U3.3@3893.8,3576.9
  Bottom Layer w7.8: v1(4289.9,3545) 4434.1,3689.2 v1(4434.1,3843.9) ; v1(4511.3,3806.8) 4573.1,3868.6 4573.1,3928.6 4634.9,3990.4 4654.9,3990.4 4664.9,4000.4 4664.9,4060.4 4575.7,4149.6 v1(4575.7,4210.5)
$1N359: CN2.4 R4.1 U1.78 U2.19 U3.4 U4.5 U5.1 | length 2494.7
  Top Layer w7.8: v1(4328.2,4029.7) 4339.9,4029.7 4358.2,4011.4 4358.2,3834.2 4358.2,3829.7 ; U1.78@4366.2,4092.3 4366.2,4059.7 v1(4376.2,4049.7) ; v1(4505.2,4288.1) 4545.2,4288.1 U4.5@4555.2,4278.1
  Top Layer w8.9: U2.19@3742.2,3767.8 v1(3801,3709) ; v1(3865,3640) 3900,3605 3901.8,3605 3913,3593.8 3913,3592 3925.3,3579.7 U3.4@3925.3,3576.9
  Top Layer w9.9: U5.1@4333.7,4779.6 4388.1,4779.6 v1(4412.1,4755.6) ; v1(4399.6,4586.5) 4399.6,4510.5 4555.2,4354.9 U4.5@4555.2,4278.1
  Top Layer w10: U3.4@3925.3,3576.9 3982.5,3634.2 v1(3983.7,3634.2) ; v1(4258,3777.2) 4289.6,3808.8 4289.6,3827.3 4292,3829.7 ; R4.1@4259.9,3819.7 4269.9,3829.7 4292,3829.7 ; 4358.2,3829.7 4292,3829.7 ; CN2.4@4523.7,3748.6 4480.5,3748.6 4415,3814.2 4385.4,3814.2 4365.4,3834.2 4358.2,3834.2 4296.5,3834.2 4292,3829.7
  Bottom Layer w7.8: v1(4328.2,4029.7) 4348.2,4049.7 v1(4376.2,4049.7) 4376.2,4069.7 4406.8,4100.3 4406.8,4139.7 4376.8,4169.7 4376.8,4229.7 4425.2,4278.1 4495.2,4278.1 v1(4505.2,4288.1)
  Bottom Layer w8.9: v1(3801,3709) 3801,3704 v1(3865,3640)
  Bottom Layer w9.9: v1(4399.6,4586.5) 4395.3,4590.8 4395.3,4738.7 v1(4412.1,4755.6)
  Bottom Layer w10: v1(3983.7,3634.2) 4115,3634.2 v1(4258,3777.2)
$1N360: R9.1 U2.11 | length 638.7
  Top Layer w8.9: U2.11@3651.1,3846.6 3665.4,3846.6 3685.4,3826.6 v1(3725.4,3826.6) ; v1(4135.4,3606.6) 4185.9,3606.6 R9.1@4189.1,3609.7
  Bottom Layer w8.9: v1(3725.4,3826.6) 3759.6,3826.6 3979.6,3606.6 v1(4135.4,3606.6)
$1N368: R5.2 R6.1 U15.4 | length 2193.7
  Top Layer w10: R6.1@3678.5,4139.9 3689,4129.4 v1(3689,4059.4) ; v1(4564.2,3969.4) 4554.2,3959.4 4554.2,3949.4 4534.2,3929.4 R5.2@4534.2,3919.4 4539.2,3914.5 4539.2,3904.4 4599.2,3844.4 v1(4699.2,3844.4) ; v1(4682.8,4394.4) 4702.8,4414.4 U15.4@4702.8,4480.5
  Bottom Layer w10: v1(3689,4059.4) 3699,4059.4 3739,4019.4 3739,3939.4 3908.6,3769.8 4174.6,3769.8 4334.2,3929.4 4414.2,3929.4 4474.2,3989.4 4544.2,3989.4 v1(4564.2,3969.4) ; v1(4682.8,4394.4) 4762,4315.2 4762,3907.1 v1(4699.2,3844.4)
$1N370: C6.2 L2.1 U15.2 | length 1515.1
  Top Layer w10: L2.1@3661,4848.5 v1(3789.7,4848.5) ; v1(4120,4884) 4197.1,4806.9 v1(4214.9,4806.9) ; v1(4215.5,4894.5) 4279.6,4958.5 4409.7,4958.5 4453.6,4914.6 C6.2@4453.6,4844.6 4592.7,4844.6 4670.2,4767.1 4670.2,4677.1 4740.2,4607.1 U15.2@4740.2,4570.9
  Bottom Layer w10: v1(3789.7,4848.5) 3825.1,4884 v1(4120,4884) ; v1(4214.9,4806.9) 4214.9,4893.8 v1(4215.5,4894.5)
$1N371: C6.1 U15.6 | length 566.8
  Top Layer w10: C6.1@4420.5,4844.6 4420.5,4783.7 4507.6,4696.6 4527.3,4696.6 v1(4703.4,4520.4) ; v1(4767.6,4524.4) 4777.6,4514.4 U15.6@4777.6,4480.5
  Bottom Layer w10: v1(4703.4,4520.4) 4707.4,4524.4 v1(4767.6,4524.4)
$1N373: D1.5 D2.2 USBC1.A4B9 USBC1.B4A9 | length 2719.9
  Top Layer w10: v1(3712.2,4010.3) 3842.2,4140.3 3842.2,4604.3 D2.2@3877.7,4639.9 ; v1(3974.9,3349) 3974.9,3322.4 4026.2,3271.1 4108.2,3271.1 4132.2,3295.2 4156.9,3295.2 ; USBC1.A4B9@4118.2,3355.4 4118.2,3333.9 4156.9,3295.2 ; v1(4203.4,3230.2) 4183.4,3250.2 4183.4,3254 ; v1(4277.2,3270.2) 4287.2,3280.2 4287.2,3300.2 ; USBC1.B4A9@4307.2,3355.4 4307.2,3330.2 4297.2,3320.2 4297.2,3310.2 4287.2,3300.2 ; v1(4424,3220.1) 4217.3,3220.1 4183.4,3254 ; D1.5@4492.2,3189.1 4492.2,3228.3 4466.5,3254 ccw(c4454.8,3243.1) 4454.8,3259.1 4328.3,3259.1 4287.2,3300.2 ; 4156.9,3295.2 4182.2,3269.8 ; 4156.9,3295.2 4162.2,3295.2 4182.2,3275.2 4182.2,3269.8 ; 4182.2,3269.8 4182.2,3255.2 4183.4,3254 ; 4182.2,3269.8 4183.4,3268.7 4183.4,3254
  Bottom Layer w10: v1(3712.2,4010.3) 3722.2,4000.3 3722.2,3860.3 3702.2,3840.3 3702.2,3770.3 3882.2,3590.3 3882.2,3441.7 v1(3974.9,3349) ; v1(4203.4,3230.2) 4237.2,3230.2 v1(4277.2,3270.2) ; v1(4424,3220.1) 4427.1,3220.1 4446.5,3239.5 v1(4479.5,3239.5)
$1N378: L1.1 U1.63 | length 482.7
  Top Layer w7.8: v1(3926.1,4321.1) 3926.1,4431.4 L1.1@3929.2,4434.5 ; v1(3980,4229.3) 3980,4179.3 4040,4119.3 4120,4119.3 4122.5,4121.8 4127.5,4121.8 4130,4119.3 U1.63@4130,4092.3
  Bottom Layer w7.8: v1(3926.1,4321.1) 3926.1,4284.3 3980,4230.3 v1(3980,4229.3)
$1N379: C17.1 C19.1 C20.1 L1.2 U1.10 U1.32 U1.51 U1.65 | length 2242.3
  Top Layer w7.8: C17.1@3917.4,4245.4 3919.7,4247.7 3957.9,4247.7 3977.9,4267.7 4027.9,4267.7 4037.9,4277.7 U1.51@4054.9,4277.7 4089,4277.7 ; L1.2@3929.2,4513.9 3977.9,4465.2 3977.9,4277.7 3987.9,4267.7 ; v1(4058.5,3935.4) 4058.5,3692.5 C19.1@4098.5,3652.5 ; v1(4099,4217.7) 4089,4227.7 4089,4277.7 ; v1(4171.5,3945.4) 4161.5,3955.4 U1.65@4161.5,4092.3 4161.5,4110.2 v1(4179,4127.7) ; U1.32@4224.5,4478.8 4224.5,4451.8 4208.3,4435.6 ; v1(4354.8,4426.9) 4354.8,4398 4319.1,4362.4 4281.5,4362.4 4208.3,4435.6 ; v1(4406.3,4334.5) 4406.3,4292.7 4421.3,4277.7 U1.10@4441.3,4277.7 ; v1(4494.5,4491.8) 4494.5,4531.1 C20.1@4553.9,4590.6 ; 4089,4277.7 4089,4316.3 4208.3,4435.6
  Bottom Layer w7.8: v1(4058.5,3935.4) 4098.5,3975.4 4141.5,3975.4 v1(4171.5,3945.4) ; v1(4099,4217.7) 4179,4137.7 v1(4179,4127.7) ; v1(4406.3,4334.5) 4354.8,4386 v1(4354.8,4426.9) 4419.7,4491.8 v1(4494.5,4491.8)
$1N380: C3.1 C4.1 C5.1 C7.1 R2.1 U1.61 | length 2732.8
  Top Layer w7.8: C7.1@3912.7,4151.7 3912.7,4156.5 3928.5,4172.3 3967.5,4172.3 4047.5,4092.3 4086.8,4092.3 ; v1(4073.3,4063.4) 4086.8,4076.9 4086.8,4092.3 ; C3.1@4102.4,3986.3 4108.5,3992.3 4108.5,4042.3 4098.5,4052.3 U1.61@4098.5,4092.3 4086.8,4092.3 ; v1(4523.4,4448.9) 4525.6,4448.9 C4.1@4578.8,4502.1
  Top Layer w10: v1(3978.5,3892.3) 4009,3861.8 R2.1@4009,3549.4 ; C3.1@4108.5,3992.3 4125.3,3975.6 v1(4125.3,3933.4) ; v1(4632.1,4335.4) 4742.1,4335.4 4948.9,4128.5 4948.9,3698.9 C5.1@4945,3695
  Bottom Layer w7.8: v1(4073.3,4063.4) 4234.6,4063.4 4248.4,4077.3 4266.6,4077.3 4272,4071.8 4319.8,4071.8 4352.1,4104.1 4352.1,4235.4 4522.1,4405.4 4523.4,4406.7 v1(4523.4,4448.9)
  Bottom Layer w10: v1(3978.5,3892.3) 4084.2,3892.3 v1(4125.3,3933.4) ; 4522.1,4405.4 4562.1,4405.4 v1(4632.1,4335.4)
$1N384: C2.1 U1.31 U12.2 | length 6190.9
  Top Layer w7.8: v1(4230.2,4515.7) 4240.2,4505.7 U1.31@4240.2,4478.8 ; v1(4343.8,4708.5) 4379.5,4708.5 C2.1@4381.2,4706.8
  Top Layer w10: 3719.63,3374.85 cw(c3708.7,3376.1) 3708.7,3365.1 3669.4,3365.1 cw(c3669.4,3376.1) 3658.4,3376.1 3658.4,3405.6 cw(c3669.4,3405.6) 3669.4,3416.6 3708.7,3416.6 cw(c3708.7,3405.6) 3719.63,3406.83 ; 3719.7,3374.9 3894.7,3374.9 ; 3719.7,3406.9 3894.7,3406.9 ; U12.2@3876.1,3710.7 3879,3707.9 cw(c3811.8,3640.7) v1(3906.8,3640.7) ; 3894.67,3374.85 ccw(c3905.6,3376.1) 3905.6,3365.1 ccw(c3929.7,3375.1) 3919.71,3350.99 3919.7,3308.7 v1(3977.9,3250.5) ; 3894.67,3406.83 cw(c3905.6,3405.6) 3905.6,3416.6 3923.4,3416.6 ccw(c3923.4,3428.8) 3932.03,3420.17 ; 3932,3420.2 3935.5,3423.8 ; 3935.59,3423.81 cw(c3946.9,3412.5) 3946.9,3428.5 ; 3946.89,3428.4 ccw(c3933.3,3461.2) 3966.1,3447.61 ; 3966.1,3447.7 3966.1,3464.1 v1(3988.3,3486.3)
  Bottom Layer w7.8: v1(4230.2,4515.7) 4343.8,4629.3 v1(4343.8,4708.5)
  Bottom Layer w10: v1(3906.8,3640.7) 3959,3588.5 cw(c3888.3,3517.8) 3988.3,3517.8 v1(3988.3,3486.3) ; v1(3977.9,3250.5) 4052.5,3250.5 ; 4052.5,3250.6 cw(c4052.5,3231.5) 4066.01,3245.01 4074.7,3245 ; 4074.76,3244.98 ccw(c4097.7,3246.7) 4096.86,3223.72 ; 4096.8,3223.7 4100.9,3219.6 ; 4100.94,3219.54 ccw(c4102,3220.6) 4102,3219.1 ; 4102,3219.2 cw(c4102,3217.7) 4103.06,3218.76 ; 4103,3218.7 4126.3,3195.4 ; 4126.39,3195.39 ccw(c4137.7,3206.7) 4137.7,3190.7 4198.8,3129.5 4336.3,3129.5 4348.4,3117.4 4349.2,3116.6 ; v1(4343.8,4708.5) 4369.2,4733.9 4369.2,4744.9 cw(c4385.2,4744.9) 4373.89,4756.21 4382.2,4764.5 ; 4348.4,3119.6 ccw(c4373,3119.6) 4348.49,3117.46 ccw(c4373,3119.6) 4392.46,3104.56 ; 4382.2,4764.46 cw(c4405.2,4764.9) 4423.42,4778.93 ; 4392.4,3104.5 4409,3106.6 4426.1,3123.6 4428.7,3123.6 ; 4423.4,4778.9 4453.3,4808.8 ccw(c4382.6,4879.5) 4482.6,4879.5 4508.8,4905.8 4508.8,5138.8 ; 4431.5,3123.6 4428.7,3123.6 ; 4509.8,5139.6 4509.8,5175.8 cw(c4519.6,5175.8) 4512.67,5182.73 ccw(c4512.1,5183.3) 4512.9,5183.3 ; 4513.2,5183.3 4554.8,5183.3 4561.3,5176.9 4576.7,5176.9 4584.6,5168.9 cw(c4513.9,5098.2) 4613.9,5098.2 4613.9,5090.8 ; 4615.3,5089.9 4671.6,5033.6 cw(c4600.9,4962.9) 4700.9,4962.9 ; 4700.32,5101.88 ccw(c4683.7,5118.5) 4707.2,5118.5 ; 4700.9,5101.2 4700.9,4962.9 ; 4703,4942.9 4713.4,4932.5 ; 4704.34,4935.54 ccw(c4712.9,4944.1) 4712.9,4932 ; 4704.4,4935.6 4700.9,4939.1 4700.9,4962.9 ; 4706.6,5171.1 4724.4,5188.8 4724.4,5234 4725,5234.7 ; 4707.3,5118.5 4707.3,5169.1 ; 4712.94,4931.97 ccw(c4712.6,4932.8) 4713.43,4932.46 ; 4725.1,5234.7 cw(c4763.6,5234.7) 4736.38,5261.92 ; 4736.3,5261.9 cw(c4736.3,5237.8) 4753.34,5254.84 ; 4753.4,5254.9 4802.5,5254.9 ; 4801.9,5254.3 4914.9,5141.2 ; 4914.91,5141.31 cw(c4913.5,5139.9) 4915.5,5139.9 ; 4917.1,5140.3 5123.4,4934 5123.4,4899 ccw(c5178,4845) 5216.63,4778.62 ; 5216.6,4778.5 5216.6,4754.1 5269.2,4701.5 ; 5269.08,4701.77 cw(c4601.9,4429.5) 5311.11,4557.11 ; 5311.1,4558.3 5311.1,4557.2 5311.1,3943 5045.6,3677.6 5045.6,3441.7 4883.5,3279.6 4820.9,3279.6 4789.2,3247.9 4651.4,3247.9 cw(c4580.7,3318.6) 4580.7,3218.6 4517.7,3155.6 4487.9,3155.6 4481.4,3162.2 4467.2,3162.2 4428.7,3123.6
$1N387: D1.3 D1.4 R7.2 USBC1.A6 | length 1212.2
  Top Layer w10: v1(4206.5,3402) 4205.6,3402.9 USBC1.A6@4205.6,3358.2 ; R7.2@4282.3,3970.6 4282.3,3879.9 v1(4302.3,3859.9) ; v1(4369.6,3385.2) 4387.7,3385.2 4529.6,3243.2 D1.4@4529.6,3189.1 4529.6,3153.7 ccw(c4545.5,3152) 4529.59,3150.3 D1.3@4529.6,3098.6 ; USBC1.A6@4205.6,3358.2 USBC1.A6@4202.8,3355.4 USBC1.A6@4205.6,3358.2
  Bottom Layer w10: v1(4206.5,3402) v1@4209.6,3405.1 ; v1(4302.3,3859.9) 4281,3838.6 4281,3568.6 4249.6,3537.3 4249.6,3459.3 4209.6,3419.3 v1@4209.6,3405.1 ; v1(4369.6,3385.2) 4359.6,3375.2 4236.6,3375.2 4209.6,3402.2 v1@4209.6,3405.1
$1N388: D1.1 D1.6 R8.2 USBC1.A7 | length 1273.9
  Top Layer w10: USBC1.A7@4222.5,3355.4 USBC1.A7@4224.8,3353.1 ; v1(4254.8,3403.1) 4244.8,3393.1 4230.6,3393.1 4224.8,3387.3 USBC1.A7@4224.8,3353.1 ; D1.1@4454.8,3098.6 D1.6@4454.8,3189.1 4454.8,3243.1 4224.8,3243.1 4204.8,3263.1 4204.8,3283.1 4224.8,3303.1 USBC1.A7@4224.8,3353.1 ; v1(4474.8,3948.2) 4474.8,4010 R8.2@4475.4,4010.6
  Bottom Layer w10: v1(4254.8,3403.1) 4254.8,3418.2 4464.8,3628.2 4464.8,3938.2 v1(4474.8,3948.2)
$1N391: R7.1 U1.67 | length 202.1
  Top Layer w7.8: U1.67@4193,4092.3 4193,4055.4 4223,4025.4 4273,4025.4 4313,3985.4 4313,3973.9 R7.1@4316.3,3970.6
$1N392: U1.79 U8.1 | length 2109.8
  Top Layer w7.8: U1.79@4382,4092.3 4382,4075.4 4422,4035.4 4477.8,4035.4 v1(4500.6,4058.1) ; v1(4532,3965.4) v1(4532,4015.4)
  Bottom Layer w7.8: U8.1@3460.7,3525.7 3655.4,3331 3655.4,3275.9 4117.6,3275.9 4142,3300.2 4292,3300.2 4322,3270.2 4392,3270.2 4422,3300.2 4422,3476.6 4482,3536.6 4482,3825.4 4532,3875.4 v1(4532,3965.4) ; v1(4500.6,4058.1) 4500.6,4046.8 v1(4532,4015.4)
$1N393: U1.80 U9.1 | length 1471.2
  Top Layer w7.8: U1.80@4397.7,4092.3 4397.7,4090.6 v1(4428.7,4059.6)
  Bottom Layer w7.8: U9.1@3232.4,4273.2 3273.3,4232.3 3447.7,4232.3 3507.7,4292.3 3617.7,4292.3 3897.5,4012.5 4167.5,4012.5 4197.7,3982.3 4397.7,3982.3 4427.7,4012.3 4427.7,4058.6 v1(4428.7,4059.6)
$1N394: U1.1 U10.1 | length 1471.3
  Top Layer w7.8: v1(4384.3,4125.9) 4394.3,4135.9 U1.1@4441.3,4135.9
  Top Layer w10: U10.1@3232.4,4533.6 3259.9,4506 3261.9,4506 cw(c3261.9,4444.2) 3294.28,4496.84 ; 3294.22,4496.88 ccw(c3334.7,4506) 3328.49,4464.97 ; 3328.5,4465 3371.8,4465 v1(3374.1,4462.7)
  Bottom Layer w7.8: v1(3374.1,4462.7) 3622.7,4462.7 4059.1,4026.3 4186.7,4026.3 ; 4187.9,4027.8 4188.4,4027.8 ; 4188.43,4027.79 cw(c4202,4010.6) 4215.57,4027.79 ; 4215.6,4027.8 4253,4027.8 cw(c4253,4025) 4254.98,4026.98 ; 4255,4025.9 4293.4,4025.9 4384.3,4116.8 v1(4384.3,4125.9)
$1N395: U1.2 U11.1 | length 1620.6
  Top Layer w7.8: U1.2@4441.3,4151.7 4460.8,4151.7 4464.3,4148.1 v1(4464.3,4061.7)
  Bottom Layer w7.8: U11.1@3236.3,4003 3315,4081.7 3704.3,4081.7 3754.3,4031.7 3754.3,3991.7 3904.3,3841.7 4224.3,3841.7 4334.3,3951.7 4414.3,3951.7 4464.3,4001.7 v1(4464.3,4061.7)
$1N398: H1.3 H2.3 U1.34 | length 1254.7
  Top Layer w7.8: v1(4123,4541.8) 4163,4501.8 4189.4,4501.8 4193,4498.2 U1.34@4193,4478.8
  Bottom Layer w7.8: v1(4123,4541.8) 4123,4581.8 4193,4651.8 4193,4984.8 H2.3@4198.5,4990.3
  Bottom Layer w10: H1.3@3731.6,5129.2 3782.7,5180.3 4174.7,5180.3 4188.5,5166.5 4188.5,5153.8 ; 4188.5,5153.88 cw(c4153.9,5129.2) 4188.5,5104.52 4188.5,5000.3 H2.3@4198.5,4990.3
$1N399: H1.4 H2.1 U1.33 | length 882.1
  Top Layer w7.8: H2.1@3998.5,4990.3 4028.7,4960 4028.7,4755.7 4116.2,4668.3 v1(4127,4668.3) ; v1(4098.7,4565.7) 4148.7,4565.7 4208.7,4505.7 U1.33@4208.7,4478.8
  Bottom Layer w7.8: v1(4098.7,4565.7) 4098.7,4640 v1(4127,4668.3)
  Bottom Layer w10: H1.4@3831.6,5129.2 3970.5,4990.3 H2.1@3998.5,4990.3
$1N400: H1.7 U1.46 | length 970.3
  Top Layer w7.8: U1.46@4054.9,4356.4 v1(4091.9,4356.4)
  Bottom Layer w7.8: v1(4091.9,4356.4) 4081.9,4346.4 4011.9,4346.4 4001.9,4356.4 4001.9,4696.4 4141.9,4836.4 4141.9,5118.9 H1.7@4131.6,5129.2
$1N401: H1.8 U1.45 | length 880.9
  Top Layer w7.8: v1(4024.9,4372.2) U1.45@4054.9,4372.2
  Bottom Layer w7.8: v1(4024.9,4372.2) 4024.9,4382.2 4144.9,4502.2 4144.9,4582.2 4241.6,4678.9 4241.6,5119.2 H1.8@4231.6,5129.2
$1N402: H1.9 U1.44 | length 885.9
  Top Layer w7.8: U1.44@4054.9,4387.9 v1(4091.9,4387.9)
  Bottom Layer w7.8: v1(4091.9,4387.9) 4081.9,4397.9 4081.9,4417.9 4161.9,4497.9 4161.9,4577.9 4331.6,4747.6 H1.9@4331.6,5129.2
$1N403: H1.10 U1.43 | length 909.1
  Top Layer w7.8: U1.43@4054.9,4403.7 4071.9,4403.7 4081.9,4413.7 v1(4111.9,4413.7)
  Bottom Layer w7.8: v1(4111.9,4413.7) 4181.9,4483.7 4181.9,4578.4 4345.4,4741.9 4345.4,5043 H1.10@4431.6,5129.2
$1N404: H1.13 U1.11 | length 966
  Top Layer w7.8: U1.11@4441.3,4293.4 4458.3,4293.4 4478.3,4313.4 v1(4478.3,4393.4)
  Bottom Layer w7.8: v1(4478.3,4393.4) 4478.3,4443.4 4728.3,4693.4 4728.3,5125.9 H1.13@4731.6,5129.2
$1N405: CARD1.5 U1.8 | length 387.2
  Top Layer w7.8: U1.8@4441.3,4246.2 4491.3,4246.2 4502.3,4235.2 v1(4502.3,4224.8) ; v1(4642,4050.9) CARD1.5@4721.5,4050.9
  Bottom Layer w7.8: v1(4502.3,4224.8) 4502.3,4190.6 v1(4642,4050.9)
$1N406: CARD1.3 U1.9 | length 331.7
  Top Layer w7.8: U1.9@4441.3,4261.9 4507.6,4261.9 v1(4512,4257.5) ; v1(4677.6,4163.2) 4703.3,4137.5 CARD1.3@4721.5,4137.5
  Bottom Layer w7.8: v1(4512,4257.5) 4583.3,4257.5 v1(4677.6,4163.2)
$1N409: CARD1.2 U1.7 | length 300.7
  Top Layer w7.8: U1.7@4441.3,4230.4 4463.8,4230.4 4505.6,4188.6 4713.7,4188.6 CARD1.2@4721.5,4180.8
$1N413: R8.1 U1.66 | length 349.9
  Top Layer w7.8: U1.66@4177.2,4092.3 4177.2,4035.4 v1(4202,4010.6) ; v1(4397,4023.1) 4414.7,4023.1 4416.3,4021.6 4430.3,4021.6 R8.1@4441.3,4010.6
  Bottom Layer w7.8: v1(4202,4010.6) 4212,4000.6 4374.4,4000.6 v1(4397,4023.1)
